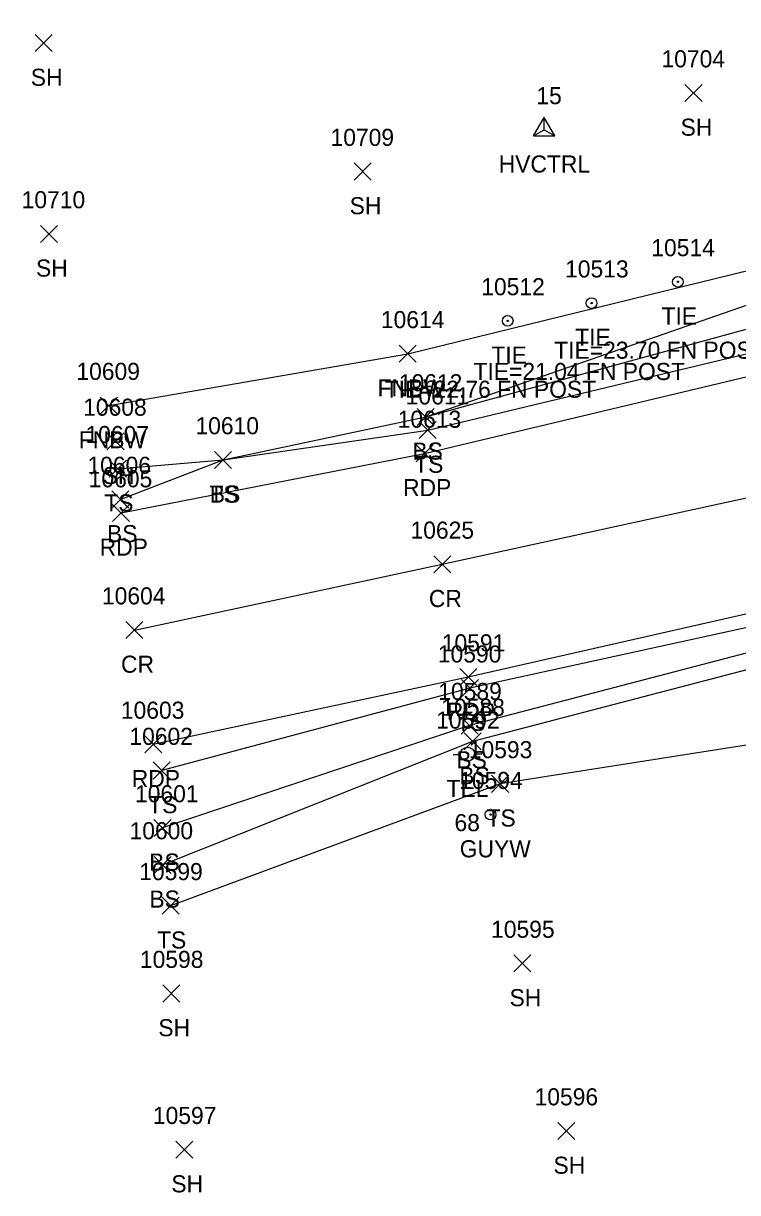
# Model space of a CAD drawing. Extents: x 1475671 to 1477951, y 592661 to 593821.
# Drawn here: x 1475670.6 to 1475754.2, y 592845.2 to 592982 of the extents above; entities that cross this region are included whole.
import ezdxf

# ---------------------------------------------------------------- set-up
doc = ezdxf.new("R2010")
doc.units = 0
for name, color, linetype in [('C_A', 7, 'Continuous'), ('C_C', 7, 'Continuous'), ('C_I', 7, 'Continuous'), ('CBP', 7, 'Continuous'), ('CPSM', 7, 'Continuous'), ('L_A', 7, 'Continuous'), ('L_I', 7, 'Continuous'), ('L_TIC', 7, 'Continuous'), ('LELB', 7, 'Continuous'), ('LFNC', 7, 'Continuous'), ('P_A', 7, 'Continuous'), ('P_I', 7, 'Continuous'), ('P_TIC', 7, 'Continuous'), ('PET', 7, 'Continuous'), ('PRC', 7, 'Continuous'), ('U_A', 7, 'Continuous'), ('U_C', 7, 'Continuous'), ('U_I', 7, 'Continuous'), ('UP', 7, 'Continuous'), ('UPGW', 7, 'Continuous')]:
    doc.layers.add(name, color=color, linetype=linetype)

msp = doc.modelspace()

# ---------------------------------------------------------------- linework, layer by layer
at = {"layer": 'CBP'}
for centre, radius in [((1475747.22, 592951.76), 0.625), ((1475747.22, 592951.76), 0.0833), ((1475737.12, 592949.27), 0.625), ((1475737.12, 592949.27), 0.0833), ((1475727.31, 592947.19), 0.625), ((1475727.31, 592947.19), 0.0833)]:
    msp.add_circle(centre, radius, dxfattribs=at)
at = {"layer": 'CPSM'}
for p, q in [((1475730.31, 592968.83), (1475731.56, 592970.99)), ((1475730.31, 592968.83), (1475731.56, 592970.99)), ((1475730.31, 592968.83), (1475731.56, 592970.99)), ((1475730.31, 592968.83), (1475731.56, 592970.99)), ((1475732.81, 592968.83), (1475731.56, 592970.99)), ((1475731.56, 592969.55), (1475731.56, 592970.99)), ((1475732.81, 592968.83), (1475731.56, 592970.99)), ((1475731.56, 592969.55), (1475731.56, 592970.99)), ((1475732.81, 592968.83), (1475731.56, 592970.99)), ((1475731.56, 592969.55), (1475731.56, 592970.99)), ((1475732.81, 592968.83), (1475731.56, 592970.99)), ((1475731.56, 592969.55), (1475731.56, 592970.99)), ((1475730.31, 592968.83), (1475731.56, 592969.55)), ((1475730.31, 592968.83), (1475731.56, 592969.55)), ((1475730.31, 592968.83), (1475731.56, 592969.55)), ((1475730.31, 592968.83), (1475731.56, 592969.55)), ((1475730.31, 592968.83), (1475732.81, 592968.83)), ((1475730.31, 592968.83), (1475732.81, 592968.83)), ((1475730.31, 592968.83), (1475732.81, 592968.83)), ((1475730.31, 592968.83), (1475732.81, 592968.83)), ((1475731.56, 592969.55), (1475731.56, 592969.55)), ((1475731.56, 592969.55), (1475732.81, 592968.83)), ((1475731.56, 592969.55), (1475731.56, 592969.55)), ((1475731.56, 592969.55), (1475732.81, 592968.83)), ((1475731.56, 592969.55), (1475731.56, 592969.55)), ((1475731.56, 592969.55), (1475732.81, 592968.83)), ((1475731.56, 592969.55), (1475731.56, 592969.55)), ((1475731.56, 592969.55), (1475732.81, 592968.83))]:
    msp.add_line(p, q, dxfattribs=at)
at = {"layer": 'L_TIC'}
for points in [[(1475672, 592978.7), (1475674, 592980.7)], [(1475674, 592978.7), (1475672, 592980.7)], [(1475748.05, 592972.86), (1475750.05, 592974.86)], [(1475750.05, 592972.86), (1475748.05, 592974.86)], [(1475709.33, 592963.67), (1475711.33, 592965.67)], [(1475711.33, 592963.67), (1475709.33, 592965.67)], [(1475672.61, 592956.37), (1475674.61, 592958.37)], [(1475674.61, 592956.37), (1475672.61, 592958.37)], [(1475714.61, 592942.34), (1475716.61, 592944.34)], [(1475716.61, 592942.34), (1475714.61, 592944.34)], [(1475679.63, 592936.28), (1475681.63, 592938.28)], [(1475681.63, 592936.28), (1475679.63, 592938.28)], [(1475716.71, 592934.95), (1475718.71, 592936.95)], [(1475718.71, 592934.95), (1475716.71, 592936.95)], [(1475716.71, 592934.95), (1475718.71, 592936.95)], [(1475718.71, 592934.95), (1475716.71, 592936.95)], [(1475716.95, 592933.41), (1475718.95, 592935.41)], [(1475718.95, 592933.41), (1475716.95, 592935.41)], [(1475680.41, 592932.09), (1475682.41, 592934.09)], [(1475682.41, 592932.09), (1475680.41, 592934.09)], [(1475692.99, 592929.92), (1475694.99, 592931.92)], [(1475694.99, 592929.92), (1475692.99, 592931.92)], [(1475692.99, 592929.92), (1475694.99, 592931.92)], [(1475694.99, 592929.92), (1475692.99, 592931.92)], [(1475680.68, 592928.89), (1475682.68, 592930.89)], [(1475682.68, 592928.89), (1475680.68, 592930.89)], [(1475680.97, 592925.29), (1475682.97, 592927.29)], [(1475682.97, 592925.29), (1475680.97, 592927.29)], [(1475721.89, 592903.21), (1475723.89, 592905.21)], [(1475723.89, 592903.21), (1475721.89, 592905.21)], [(1475721.85, 592898.83), (1475723.85, 592900.83)], [(1475723.85, 592898.83), (1475721.85, 592900.83)], [(1475722.2, 592896.97), (1475724.2, 592898.97)], [(1475724.2, 592896.97), (1475722.2, 592898.97)], [(1475685.82, 592893.57), (1475687.82, 592895.57)], [(1475687.82, 592893.57), (1475685.82, 592895.57)], [(1475725.42, 592892.01), (1475727.42, 592894.01)], [(1475727.42, 592892.01), (1475725.42, 592894.01)], [(1475685.91, 592886.85), (1475687.91, 592888.85)], [(1475687.91, 592886.85), (1475685.91, 592888.85)], [(1475685.93, 592882.52), (1475687.93, 592884.52)], [(1475687.93, 592882.52), (1475685.93, 592884.52)], [(1475686.86, 592877.74), (1475688.86, 592879.74)], [(1475688.86, 592877.74), (1475686.86, 592879.74)], [(1475728.03, 592870.99), (1475730.03, 592872.99)], [(1475730.03, 592870.99), (1475728.03, 592872.99)], [(1475686.93, 592867.47), (1475688.93, 592869.47)], [(1475688.93, 592867.47), (1475686.93, 592869.47)], [(1475733.17, 592851.38), (1475735.17, 592853.38)], [(1475735.17, 592851.38), (1475733.17, 592853.38)], [(1475688.45, 592849.2), (1475690.45, 592851.2)], [(1475690.45, 592849.2), (1475688.45, 592851.2)]]:
    msp.add_lwpolyline(points, dxfattribs=at)
at = {"layer": 'LELB'}
for points in [[(1475681.97, 592926.29), (1475693.99, 592930.92), (1475717.71, 592935.95), (1475764.49, 592948.74), (1475792.84, 592955.38), (1475826.76, 592965.2), (1475839.14, 592967.57), (1475847.44, 592968.45), (1475896, 592975.83), (1475948.75, 592985.5), (1475992.67, 592993.57), (1476057.44, 593003.96), (1476113.1, 593013.57), (1476163.64, 593021.28), (1476215.98, 593029.82), (1476272.69, 593037.85), (1476322.72, 593046.24), (1476372.45, 593058.02), (1476374.59, 593060.62), (1476398.56, 593065.83), (1476415.47, 593071.31), (1476457.34, 593084.84)], [(1475681.68, 592929.89), (1475693.99, 592930.92), (1475717.95, 592934.41), (1475766.45, 592946.03), (1475793.6, 592952.64), (1475827.75, 592961.96), (1475839.66, 592963.32), (1475897.61, 592972.89), (1475949.51, 592982.21), (1475996.32, 592990.67), (1476057.58, 593001.03), (1476113.5, 593010.46), (1476164.33, 593018.66), (1476216.45, 593027.16), (1476273.17, 593035.57), (1476322.97, 593043.9), (1476372.64, 593054.79), (1476374.63, 593058.12)], [(1475717.71, 592935.95), (1475763.09, 592951.77), (1475792.41, 592958.23), (1475826.76, 592965.2)], [(1475774.25, 592915.44), (1475722.89, 592904.21), (1475686.82, 592894.57)], [(1475770.57, 592912.32), (1475722.85, 592899.83), (1475686.91, 592887.85)], [(1475770.57, 592912.32), (1475770.97, 592910.46), (1475723.2, 592897.97), (1475686.93, 592883.52)], [(1475777.6, 592901.06), (1475726.42, 592893.01), (1475687.86, 592878.74)]]:
    msp.add_lwpolyline(points, dxfattribs=at)
at = {"layer": 'LFNC'}
msp.add_lwpolyline([(1475680.63, 592937.28), (1475715.61, 592943.34), (1475763.84, 592955.14), (1475791.92, 592961.08), (1475824.89, 592967.76), (1475839.13, 592970.46), (1475847.47, 592971.97), (1475895.02, 592980.45), (1475948.31, 592989.25), (1475993.78, 592996.67), (1476056.99, 593006.94), (1476113.81, 593016.03), (1476164.23, 593025.08), (1476215.07, 593032.59), (1476272.43, 593042.08), (1476322.23, 593049.67), (1476368.09, 593057.49), (1476372.45, 593058.02), (1476374.63, 593058.12), (1476399.83, 593064.01), (1476415.89, 593069.22), (1476458.99, 593083.01), (1476499.73, 593099.84)], dxfattribs=at)
at = {"layer": 'P_TIC'}
for points in [[(1475716.58, 592930.68), (1475718.58, 592932.68)], [(1475718.58, 592930.68), (1475716.58, 592932.68)], [(1475681.06, 592923.71), (1475683.06, 592925.71)], [(1475683.06, 592923.71), (1475681.06, 592925.71)], [(1475718.65, 592917.7), (1475720.65, 592919.7)], [(1475720.65, 592917.7), (1475718.65, 592919.7)], [(1475682.62, 592910.01), (1475684.62, 592912.01)], [(1475684.62, 592910.01), (1475682.62, 592912.01)], [(1475721.69, 592904.51), (1475723.69, 592906.51)], [(1475723.69, 592904.51), (1475721.69, 592906.51)], [(1475684.82, 592896.63), (1475686.82, 592898.63)], [(1475686.82, 592896.63), (1475684.82, 592898.63)]]:
    msp.add_lwpolyline(points, dxfattribs=at)
at = {"layer": 'PET'}
for points in [[(1475682.06, 592924.71), (1475717.58, 592931.68), (1475766.32, 592943.31), (1475794.98, 592949.79), (1475825.77, 592956.33), (1475844.1, 592960.26), (1475899.54, 592970.95), (1475949.72, 592980.21), (1475996.45, 592988.43), (1476057.84, 592998.4), (1476110.05, 593006.96), (1476164.18, 593015.73), (1476216.75, 593023.76), (1476273.83, 593032.32), (1476323.32, 593041.42), (1476373.65, 593052.29), (1476409.24, 593061.35), (1476416.16, 593063.9), (1476459.25, 593078.48), (1476508.39, 593100.17)], [(1476521.33, 593044.37), (1476462.5, 593038.2), (1476408.69, 593032.05), (1476367.34, 593022.2), (1476318.64, 593012.07), (1476266.69, 593003.36), (1476216.58, 592995.35), (1476163.86, 592987.33), (1476119.65, 592980.05), (1476101.05, 592977.22), (1476048.95, 592968.83), (1475997.04, 592960.32), (1475947.8, 592951.63), (1475898.72, 592942.8), (1475855.26, 592933.74), (1475801.94, 592923.33), (1475788.88, 592919.68), (1475771.17, 592916.5), (1475722.69, 592905.51), (1475685.82, 592897.63)]]:
    msp.add_lwpolyline(points, dxfattribs=at)
at = {"layer": 'PRC'}
msp.add_lwpolyline([(1475683.62, 592911.01), (1475719.65, 592918.7), (1475759.33, 592927.39), (1475790.86, 592934.39), (1475834.03, 592943.87), (1475901.67, 592957.18), (1475953.57, 592967.02), (1476000.12, 592975.16), (1476059.54, 592984.65), (1476113.3, 592993.58), (1476166.39, 593001.74), (1476218.93, 593009.6), (1476277, 593018.86), (1476325.59, 593027.6), (1476377.06, 593038.84), (1476415.44, 593049.14), (1476421.8, 593050.95), (1476461.98, 593064.62), (1476520.7, 593090.52)], dxfattribs=at)
at = {"layer": 'UP'}
for p, q in [((1475720.94, 592896.46), (1475721.76, 592896.46)), ((1475722.6, 592896.47), (1475722.6, 592896.47)), ((1475724.26, 592896.47), (1475723.43, 592896.47)), ((1475723.43, 592896.47), (1475723.43, 592896.47)), ((1475724.26, 592896.47), (1475724.26, 592896.47))]:
    msp.add_line(p, q, dxfattribs=at)
msp.add_circle((1475722.6, 592896.47), 0.833, dxfattribs=at)
at = {"layer": 'UPGW'}
for radius in [0.625, 0.0833]:
    msp.add_circle((1475725.3, 592889.41), radius, dxfattribs=at)

# ---------------------------------------------------------------- texts
at = {"layer": 'C_A'}
for s, p in [('HVCTRL', (1475726.25, 592964.55)), ('HVCTRL', (1475726.25, 592964.55)), ('HVCTRL', (1475726.25, 592964.55)), ('HVCTRL', (1475726.25, 592964.55)), ('TIE', (1475745.3, 592946.76)), ('TIE', (1475735.2, 592944.27)), ('TIE', (1475725.39, 592942.19))]:
    msp.add_text(s, height=2, dxfattribs=at).set_placement(p)
at = {"layer": 'C_C'}
for s, p in [('TIE=23.70 FN POST', (1475732.75, 592942.76)), ('TIE=21.04 FN POST', (1475723.3, 592940.27)), ('TIE=22.76 FN POST', (1475712.91, 592938.19))]:
    msp.add_text(s, height=2, dxfattribs=at).set_placement(p)
at = {"layer": 'C_I'}
for s, p in [('15', (1475730.66, 592972.55)), ('15', (1475730.66, 592972.55)), ('15', (1475730.66, 592972.55)), ('15', (1475730.66, 592972.55)), ('10514', (1475744.11, 592954.76)), ('10513', (1475734.02, 592952.27)), ('10512', (1475724.21, 592950.19))]:
    msp.add_text(s, height=2, dxfattribs=at).set_placement(p)
at = {"layer": 'L_A'}
for s, p in [('SH', (1475671.49, 592974.7)), ('SH', (1475747.54, 592968.86)), ('SH', (1475708.81, 592959.67)), ('SH', (1475672.1, 592952.37)), ('FNBW', (1475712.08, 592938.34)), ('FNBW', (1475677.11, 592932.28)), ('BS', (1475716.15, 592930.95)), ('BS', (1475716.15, 592930.95)), ('TS', (1475716.36, 592929.41)), ('SH', (1475679.9, 592928.09)), ('TS', (1475692.4, 592925.92)), ('BS', (1475692.44, 592925.92)), ('TS', (1475680.09, 592924.89)), ('BS', (1475680.41, 592921.29)), ('TS', (1475721.3, 592899.21)), ('BS', (1475721.3, 592894.83)), ('BS', (1475721.64, 592892.97)), ('TS', (1475685.23, 592889.57)), ('TS', (1475724.83, 592888.01)), ('BS', (1475685.35, 592882.85)), ('BS', (1475685.37, 592878.52)), ('TS', (1475686.27, 592873.74)), ('SH', (1475727.52, 592866.99)), ('SH', (1475686.42, 592863.47)), ('SH', (1475732.66, 592847.38)), ('SH', (1475687.94, 592845.2))]:
    msp.add_text(s, height=2, dxfattribs=at).set_placement(p)
at = {"layer": 'L_I'}
for s, p in [('10704', (1475745.3, 592976.86)), ('10709', (1475706.57, 592967.67)), ('10710', (1475670.42, 592960.37)), ('10614', (1475712.46, 592946.34)), ('10609', (1475676.83, 592940.28)), ('10612', (1475714.56, 592938.95)), ('10612', (1475714.56, 592938.95)), ('10611', (1475715.37, 592937.41)), ('10608', (1475677.62, 592936.09)), ('10610', (1475690.76, 592933.92)), ('10610', (1475690.76, 592933.92)), ('10607', (1475677.89, 592932.89)), ('10606', (1475678.12, 592929.29)), ('10590', (1475719.13, 592907.21)), ('10589', (1475719.18, 592902.83)), ('10588', (1475719.53, 592900.97)), ('10602', (1475683.03, 592897.57)), ('10593', (1475722.75, 592896.01)), ('10601', (1475683.69, 592890.85)), ('10600', (1475683.05, 592886.52)), ('10599', (1475684.18, 592881.74)), ('10595', (1475725.36, 592874.99)), ('10598', (1475684.26, 592871.47)), ('10596', (1475730.45, 592855.38)), ('10597', (1475685.78, 592853.2))]:
    msp.add_text(s, height=2, dxfattribs=at).set_placement(p)
at = {"layer": 'P_A'}
for s, p in [('RDP', (1475715.06, 592926.68)), ('RDP', (1475679.55, 592919.71)), ('CR', (1475718.08, 592913.7)), ('CR', (1475682.05, 592906.01)), ('RDP', (1475720.18, 592900.51)), ('RDP', (1475683.31, 592892.63))]:
    msp.add_text(s, height=2, dxfattribs=at).set_placement(p)
at = {"layer": 'P_I'}
for s, p in [('10613', (1475714.43, 592934.68)), ('10605', (1475678.27, 592927.71)), ('10625', (1475715.93, 592921.7)), ('10604', (1475679.82, 592914.01)), ('10591', (1475719.59, 592908.51)), ('10603', (1475682.03, 592900.63))]:
    msp.add_text(s, height=2, dxfattribs=at).set_placement(p)
at = {"layer": 'U_A'}
for s, p in [('TEL', (1475720.15, 592891.47)), ('GUYW', (1475721.69, 592884.41))]:
    msp.add_text(s, height=2, dxfattribs=at).set_placement(p)
at = {"layer": 'U_C'}
msp.add_text('68', height=2, dxfattribs=at).set_placement((1475721.08, 592887.47))
at = {"layer": 'U_I'}
for s, p in [('10592', (1475718.93, 592899.47)), ('10594', (1475721.63, 592892.41))]:
    msp.add_text(s, height=2, dxfattribs=at).set_placement(p)

doc.saveas('drawing.dxf')
